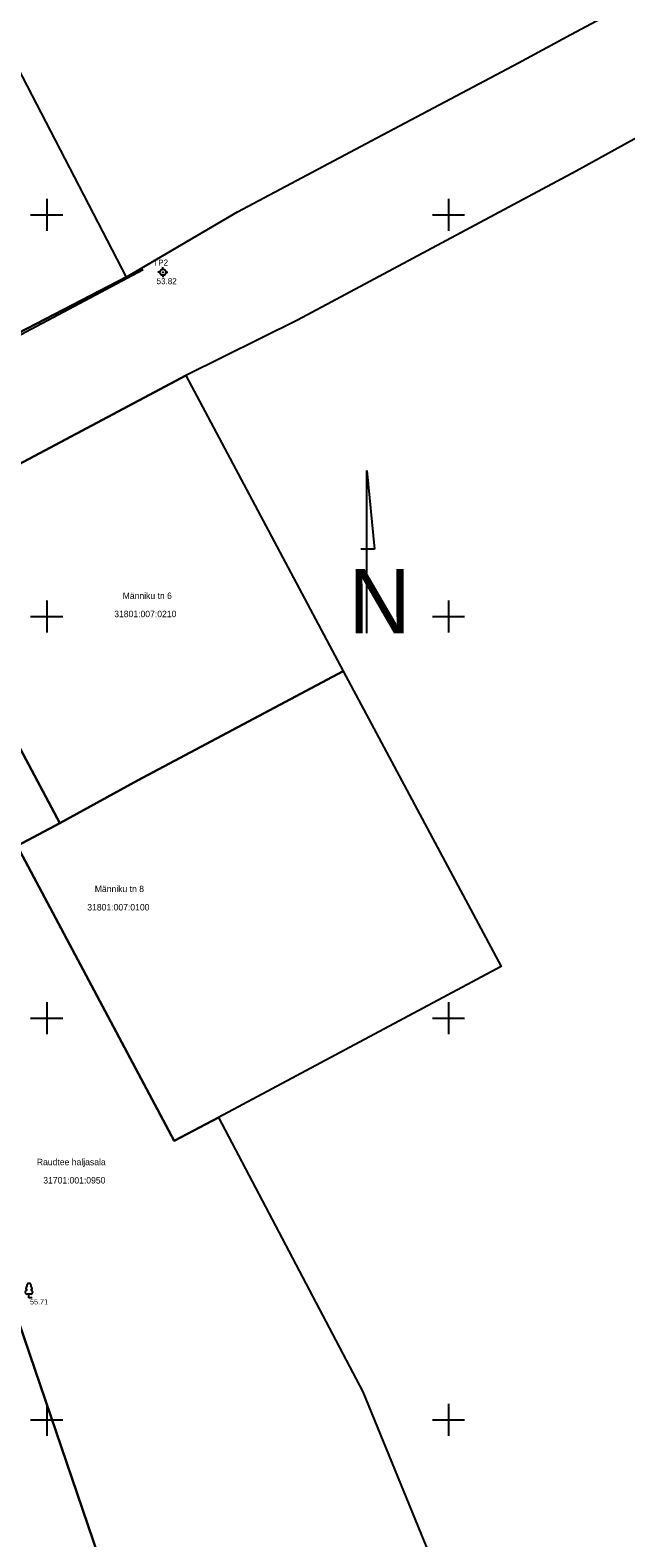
# Model space of a CAD drawing. Extents: x 542320 to 543602, y 6558748 to 6559969.
# Drawn here: x 542647.9 to 542722.1, y 6559235.3 to 6559423 of the extents above; entities that cross this region are included whole.
import ezdxf

# ---------------------------------------------------------------- set-up
doc = ezdxf.new("R2010")
doc.units = 0
for name, color, linetype in [('ALUSVORK', 7, 'Continuous'), ('KORGUS-EH2000', 7, 'Continuous'), ('MPOHULIIN', 7, 'Continuous'), ('PIIR', 7, 'Continuous'), ('PUU', 7, 'Continuous'), ('VORK', 7, 'Continuous'), ('VORMISTUS', 7, 'Continuous')]:
    doc.layers.add(name, color=color, linetype=linetype)

# ---------------------------------------------------------------- blocks, each defined once
blk = doc.blocks.new('VKORIS')
for p, q in [((0, 4), (0, -4)), ((-4, 0), (4, 0))]:
    blk.add_line(p, q)
blk = doc.blocks.new('POHINOOL')
for points in [[(0, 0), (0, 40.49)], [(0, 40.49), (1.93, 20.88)], [(1.93, 20.88), (-1.43, 20.88)]]:
    blk.add_lwpolyline(points)
blk.add_text('N', height=16).set_placement((-4.53, -0.1))
blk = doc.blocks.new('LEHTP1')
for p, q in [((0.48, 0.95), (-0.48, 0.95)), ((0, 0), (0, 0.95)), ((0.76, 0), (0, 0))]:
    blk.add_line(p, q)
for centre, radius, start, end in [((-0.47, 1.42), 0.475, 90.0016, 269.3953), ((-0.34, 2.35), 0.465, 109.0217, 253.1415), ((0, 3.04), 0.554, 332.5799, 207.4201), ((0.34, 2.35), 0.465, 286.8508, 70.9859), ((0.47, 1.42), 0.475, 270.6047, 89.9984)]:
    blk.add_arc(centre, radius, start, end)
blk = doc.blocks.new('SPYMAR')
for p, q in [((-0.75, 0), (-1.25, 0)), ((0, 0.75), (0, 1.25)), ((0.75, 0), (1.25, 0)), ((0, -0.75), (0, -1.25))]:
    blk.add_line(p, q)
for radius in [0.75, 0.044]:
    blk.add_circle((0, 0), radius)

msp = doc.modelspace()

# ---------------------------------------------------------------- linework, layer by layer
at = {"layer": 'MPOHULIIN'}
msp.add_lwpolyline([(542661.99, 6559393.16), (542622.29, 6559372.06), (542620.51, 6559378.26)], dxfattribs=at)
at = {"layer": 'PIIR'}
for points in [[(542741.15, 6559419.37), (542715.89, 6559405.45), (542681.21, 6559386.88), (542667.3, 6559379.98), (542641.94, 6559366.51), (542632.02, 6559361.13), (542612.16, 6559350.51), (542599.76, 6559343.89), (542597.79, 6559348.5), (542591.81, 6559358.92), (542604.23, 6559363.42), (542605.82, 6559364.28), (542625.12, 6559374.24), (542659.87, 6559392.24), (542673.76, 6559400.37), (542691.07, 6559409.58), (542708.69, 6559418.93), (542715.22, 6559422.45), (542743.96, 6559437.79)], [(542607.38, 6559406.52), (542613.93, 6559409.96), (542642.79, 6559425.13), (542659.87, 6559392.24), (542625.12, 6559374.24), (542607.38, 6559406.52)], [(542632.02, 6559361.13), (542641.94, 6559366.51), (542667.3, 6559379.98), (542686.87, 6559343.19), (542661.3, 6559329.57), (542651.63, 6559324.28), (542632.02, 6559361.13)], [(542632.63, 6559302.87), (542612.16, 6559350.51), (542632.02, 6559361.13), (542651.63, 6559324.28), (542646.33, 6559321.44), (542665.85, 6559284.72), (542671.39, 6559287.65), (542689.34, 6559253.48), (542704.9, 6559215.47), (542674.63, 6559203.23), (542672.45, 6559208.6), (542665.71, 6559205.86), (542632.63, 6559302.87)], [(542612.16, 6559350.51), (542632.63, 6559302.87), (542665.71, 6559205.86), (542667.87, 6559200.49), (542682.31, 6559164.31), (542683.94, 6559160.9), (542699.54, 6559124.27), (542718.47, 6559078.4), (542700.92, 6559090.29), (542700.43, 6559093.84), (542680, 6559143.81), (542637.46, 6559233.17), (542624.28, 6559266.08), (542619.08, 6559298.96), (542599.76, 6559343.89), (542612.16, 6559350.51)], [(542665.85, 6559284.72), (542646.33, 6559321.44), (542651.63, 6559324.28), (542661.3, 6559329.57), (542686.87, 6559343.19), (542706.55, 6559306.41), (542671.39, 6559287.65), (542665.85, 6559284.72)]]:
    msp.add_lwpolyline(points, dxfattribs=at)

# ---------------------------------------------------------------- block references
at = {"layer": 'ALUSVORK', "xscale": 0.5, "yscale": 0.5}
msp.add_blockref('SPYMAR', (542664.46, 6559392.84), dxfattribs=at)
at = {"layer": 'PUU', "xscale": 0.5, "yscale": 0.5}
msp.add_blockref('LEHTP1', (542647.79, 6559265.18), dxfattribs=at)
at = {"layer": 'VORK', "xscale": 0.5, "yscale": 0.5}
for p in [(542650, 6559400), (542700, 6559400), (542650, 6559350), (542700, 6559350), (542650, 6559300), (542700, 6559300), (542650, 6559250), (542700, 6559250)]:
    msp.add_blockref('VKORIS', p, dxfattribs=at)
at = {"layer": 'VORMISTUS', "xscale": 0.5, "yscale": 0.5}
msp.add_blockref('POHINOOL', (542689.82, 6559347.94), dxfattribs=at)

# ---------------------------------------------------------------- texts
at = {"layer": 'ALUSVORK'}
for s, p in [('TP2', (542663.26, 6559393.68)), ('53.82', (542663.67, 6559391.36))]:
    msp.add_text(s, height=0.75, dxfattribs=at).set_placement(p)
at = {"layer": 'KORGUS-EH2000'}
msp.add_text('55.71', height=0.65, dxfattribs=at).set_placement((542647.92, 6559264.36))
at = {"layer": 'PIIR'}
for s, p in [('Männiku tn 6', (542659.45, 6559352.18)), ('31801:007:0210', (542658.4, 6559349.91)), ('Männiku tn 8', (542655.98, 6559315.69)), ('31801:007:0100', (542655.05, 6559313.4)), ('Raudtee haljasala', (542648.77, 6559281.69)), ('31701:001:0950', (542649.57, 6559279.41))]:
    msp.add_text(s, height=0.8, dxfattribs=at).set_placement(p)

doc.saveas('drawing.dxf')
